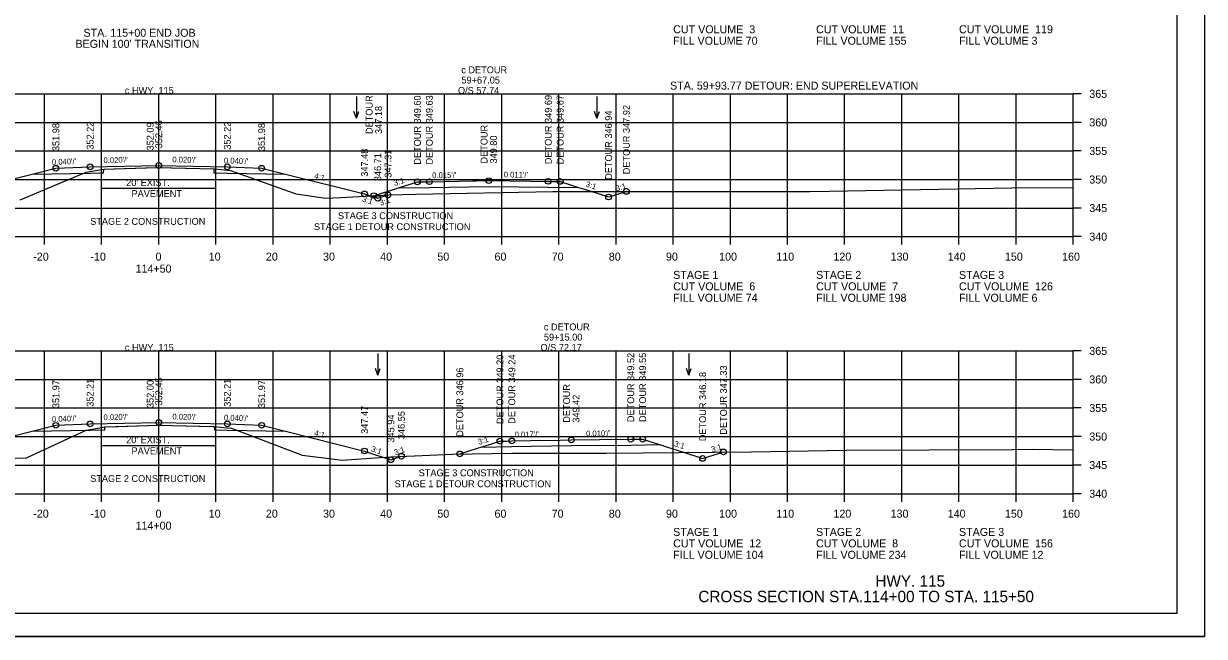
# Model space of a CAD drawing. Extents: x 1630712 to 1632516, y 782146 to 785403.
# Drawn here: x 1632309.3 to 1632515.9, y 784976.7 to 785083.9 of the extents above; entities that cross this region are included whole.
import ezdxf

# ---------------------------------------------------------------- set-up
doc = ezdxf.new("R2010")
doc.units = 0
for name, color, linetype in [('Notes', 7, 'Continuous'), ('R_Alt Surface', 7, 'Continuous'), ('R_Annot', 7, 'Continuous'), ('R_Axis', 7, 'Continuous'), ('R_Axis Annot', 7, 'Continuous'), ('R_Border', 7, 'Continuous'), ('R_Detour Subgrade', 7, 'Continuous'), ('R_Detour Surface', 7, 'Continuous'), ('R_Draft', 7, 'Continuous'), ('R_Exist Surface', 7, 'Continuous'), ('R_Fin Surface', 7, 'Continuous'), ('R_Grid', 7, 'Continuous'), ('R_No Plot', 7, 'Continuous'), ('R_Water Annot', 7, 'Continuous'), ('R_Xsect Elev', 7, 'Continuous'), ('R_Xsect Elev Detour', 7, 'Continuous'), ('R_Xsect Slope', 7, 'Continuous')]:
    doc.layers.add(name, color=color, linetype=linetype)

msp = doc.modelspace()

# ---------------------------------------------------------------- linework, layer by layer
at = {"layer": 'Notes'}
for p, q in [((1632322.96, 785053.45), (1632322.96, 785056.85)), ((1632342.96, 785053.45), (1632342.96, 785056.85)), ((1632322.96, 785055.15), (1632342.96, 785055.15)), ((1632322.96, 785008.41), (1632322.96, 785011.81)), ((1632322.96, 785010.11), (1632342.96, 785010.11)), ((1632342.96, 785008.41), (1632342.96, 785011.81))]:
    msp.add_line(p, q, dxfattribs=at)
at = {"layer": 'R_Alt Surface'}
for points in [[(1632310.79, 785057.59), (1632320.96, 785057.79), (1632323.28, 785057.83), (1632323.33, 785058.45), (1632332.68, 785058.74), (1632342.57, 785058.52), (1632342.62, 785057.84), (1632344.96, 785057.79), (1632355.14, 785057.59)], [(1632310.79, 785012.58), (1632320.96, 785012.78), (1632323.5, 785012.83), (1632323.55, 785013.35), (1632332.87, 785013.65), (1632342.67, 785013.4), (1632342.72, 785012.82), (1632344.96, 785012.78), (1632355.14, 785012.58)]]:
    msp.add_lwpolyline(points, dxfattribs=at)
at = {"layer": 'R_Axis'}
for p, q in [((1632492.96, 785046.65), (1632492.96, 785071.65)), ((1632494.36, 785071.65), (1632492.96, 785071.65)), ((1632494.36, 785066.65), (1632492.96, 785066.65)), ((1632494.36, 785061.65), (1632492.96, 785061.65)), ((1632494.36, 785056.65), (1632492.96, 785056.65)), ((1632494.36, 785051.65), (1632492.96, 785051.65)), ((1632212.96, 785046.65), (1632492.96, 785046.65)), ((1632312.96, 785045.25), (1632312.96, 785046.65)), ((1632322.96, 785045.25), (1632322.96, 785046.65)), ((1632332.96, 785045.25), (1632332.96, 785046.65)), ((1632342.96, 785045.25), (1632342.96, 785046.65)), ((1632352.96, 785045.25), (1632352.96, 785046.65)), ((1632362.96, 785045.25), (1632362.96, 785046.65)), ((1632372.96, 785045.25), (1632372.96, 785046.65)), ((1632382.96, 785045.25), (1632382.96, 785046.65)), ((1632392.96, 785045.25), (1632392.96, 785046.65)), ((1632402.96, 785045.25), (1632402.96, 785046.65)), ((1632412.96, 785045.25), (1632412.96, 785046.65)), ((1632422.96, 785045.25), (1632422.96, 785046.65)), ((1632432.96, 785045.25), (1632432.96, 785046.65)), ((1632442.96, 785045.25), (1632442.96, 785046.65)), ((1632452.96, 785045.25), (1632452.96, 785046.65)), ((1632462.96, 785045.25), (1632462.96, 785046.65)), ((1632472.96, 785045.25), (1632472.96, 785046.65)), ((1632482.96, 785045.25), (1632482.96, 785046.65)), ((1632492.96, 785045.25), (1632492.96, 785046.65)), ((1632494.36, 785046.65), (1632492.96, 785046.65)), ((1632492.96, 785001.65), (1632492.96, 785026.65)), ((1632494.36, 785026.65), (1632492.96, 785026.65)), ((1632494.36, 785021.65), (1632492.96, 785021.65)), ((1632494.36, 785016.65), (1632492.96, 785016.65)), ((1632494.36, 785011.65), (1632492.96, 785011.65)), ((1632494.36, 785006.65), (1632492.96, 785006.65)), ((1632212.96, 785001.65), (1632492.96, 785001.65)), ((1632312.96, 785000.25), (1632312.96, 785001.65)), ((1632322.96, 785000.25), (1632322.96, 785001.65)), ((1632332.96, 785000.25), (1632332.96, 785001.65)), ((1632342.96, 785000.25), (1632342.96, 785001.65)), ((1632352.96, 785000.25), (1632352.96, 785001.65)), ((1632362.96, 785000.25), (1632362.96, 785001.65)), ((1632372.96, 785000.25), (1632372.96, 785001.65)), ((1632382.96, 785000.25), (1632382.96, 785001.65)), ((1632392.96, 785000.25), (1632392.96, 785001.65)), ((1632402.96, 785000.25), (1632402.96, 785001.65)), ((1632412.96, 785000.25), (1632412.96, 785001.65)), ((1632422.96, 785000.25), (1632422.96, 785001.65)), ((1632432.96, 785000.25), (1632432.96, 785001.65)), ((1632442.96, 785000.25), (1632442.96, 785001.65)), ((1632452.96, 785000.25), (1632452.96, 785001.65)), ((1632462.96, 785000.25), (1632462.96, 785001.65)), ((1632472.96, 785000.25), (1632472.96, 785001.65)), ((1632482.96, 785000.25), (1632482.96, 785001.65)), ((1632492.96, 785000.25), (1632492.96, 785001.65)), ((1632494.36, 785001.65), (1632492.96, 785001.65))]:
    msp.add_line(p, q, dxfattribs=at)
at = {"layer": 'R_Border'}
for q in [(1632511.14, 785186.11), (1632194.96, 784980.65)]:
    msp.add_line((1632511.14, 784980.65), q, dxfattribs=at)
at = {"layer": 'R_Detour Subgrade'}
for points in [[(1632374.88, 785055.19), (1632380.3, 785055.27), (1632390.7, 785055.45), (1632401.11, 785055.33), (1632406.39, 785055.28)], [(1632389.32, 785009.79), (1632394.73, 785009.88), (1632405.14, 785010.07), (1632415.54, 785010.17), (1632420.64, 785010.23)]]:
    msp.add_lwpolyline(points, dxfattribs=at)
at = {"layer": 'R_Detour Surface'}
for points in [[(1632370.59, 785053.82), (1632371.64, 785054.16), (1632374.88, 785055.19), (1632378.03, 785056.18), (1632378.21, 785056.24), (1632378.31, 785056.24), (1632380.05, 785056.27), (1632380.3, 785056.27), (1632387.9, 785056.4), (1632388.49, 785056.41), (1632390.69, 785056.45), (1632390.7, 785056.45), (1632390.7, 785056.45), (1632398.08, 785056.36), (1632401.11, 785056.33), (1632402.25, 785056.32), (1632403.19, 785056.31), (1632404.99, 785055.73), (1632406.39, 785055.28), (1632406.79, 785055.15), (1632407.02, 785055.08), (1632408.37, 785054.65), (1632411.66, 785053.59), (1632412.13, 785053.74), (1632414.77, 785054.57)], [(1632385.63, 785008.61), (1632385.81, 785008.67), (1632387.12, 785009.09), (1632388.92, 785009.66), (1632389.32, 785009.79), (1632389.89, 785009.97), (1632392.65, 785010.85), (1632393.86, 785010.87), (1632394.73, 785010.88), (1632398.05, 785010.94), (1632403.16, 785011.03), (1632405.14, 785011.07), (1632405.15, 785011.07), (1632405.16, 785011.07), (1632410.06, 785011.11), (1632415.54, 785011.17), (1632416.56, 785011.18), (1632417.62, 785011.19), (1632419.82, 785010.49), (1632420.64, 785010.23), (1632421.15, 785010.06), (1632421.26, 785010.03), (1632421.99, 785009.79), (1632423.5, 785009.31), (1632427.29, 785008.09), (1632428.11, 785007.83), (1632430.91, 785008.71), (1632431.67, 785008.95)]]:
    msp.add_lwpolyline(points, dxfattribs=at)
at = {"layer": 'R_Exist Surface'}
for points in [[(1632308.69, 785053.12), (1632318.86, 785057.38), (1632320.24, 785057.94), (1632322.24, 785058.26), (1632323.33, 785058.45), (1632332.44, 785058.74), (1632332.68, 785058.74), (1632332.93, 785058.74), (1632342.57, 785058.52), (1632342.69, 785058.5), (1632345.52, 785058.22), (1632356.47, 785054.32), (1632356.81, 785054.2), (1632356.96, 785054.17), (1632362.18, 785053.37), (1632364.83, 785053.51), (1632373.23, 785053.97), (1632377.91, 785054.07), (1632401.93, 785054.56), (1632402.15, 785054.56), (1632402.26, 785054.57), (1632404.14, 785054.57), (1632446.79, 785054.57), (1632450.27, 785054.61), (1632482.2, 785055.18), (1632492.96, 785055.27)], [(1632304.03, 785007.76), (1632309.82, 785007.95), (1632317.08, 785011.32), (1632320.26, 785012.77), (1632322.63, 785013.19), (1632323.55, 785013.35), (1632325.83, 785013.43), (1632332.87, 785013.65), (1632340.02, 785013.47), (1632342.67, 785013.4), (1632344.84, 785013.19), (1632345.66, 785013.1), (1632349.17, 785011.79), (1632358.05, 785008.39), (1632363.21, 785007.75), (1632365.03, 785007.49), (1632371.63, 785007.99), (1632373.68, 785008.12), (1632384.41, 785008.59), (1632394.72, 785008.77), (1632411.25, 785008.74), (1632436.67, 785009), (1632453.23, 785009.26), (1632482.27, 785009.39), (1632485.78, 785009.43), (1632492.96, 785009.3)]]:
    msp.add_lwpolyline(points, dxfattribs=at)
at = {"layer": 'R_Fin Surface'}
for points in [[(1632291.9, 785053.15), (1632292.96, 785052.8), (1632296.96, 785054.13), (1632310.79, 785057.59), (1632314.96, 785058.63), (1632320.96, 785058.87), (1632332.96, 785059.11), (1632344.96, 785058.87), (1632350.96, 785058.63), (1632355.14, 785057.59), (1632368.96, 785054.13), (1632371.27, 785053.36), (1632373.07, 785053.96)], [(1632290.83, 785008.01), (1632292.24, 785007.55), (1632296.96, 785009.12), (1632310.79, 785012.58), (1632314.96, 785013.62), (1632320.96, 785013.86), (1632332.96, 785014.1), (1632344.96, 785013.86), (1632350.96, 785013.62), (1632355.14, 785012.58), (1632368.96, 785009.12), (1632373.57, 785007.59), (1632375.41, 785008.2)]]:
    msp.add_lwpolyline(points, dxfattribs=at)
at = {"layer": 'R_Grid'}
for p, q in [((1632212.96, 785071.65), (1632492.96, 785071.65)), ((1632312.96, 785046.65), (1632312.96, 785071.65)), ((1632322.96, 785046.65), (1632322.96, 785071.65)), ((1632332.96, 785046.65), (1632332.96, 785071.65)), ((1632342.96, 785046.65), (1632342.96, 785071.65)), ((1632352.96, 785046.65), (1632352.96, 785071.65)), ((1632362.96, 785046.65), (1632362.96, 785071.65)), ((1632372.96, 785046.65), (1632372.96, 785071.65)), ((1632382.96, 785046.65), (1632382.96, 785071.65)), ((1632392.96, 785046.65), (1632392.96, 785071.65)), ((1632402.96, 785046.65), (1632402.96, 785071.65)), ((1632412.96, 785046.65), (1632412.96, 785071.65)), ((1632422.96, 785046.65), (1632422.96, 785071.65)), ((1632432.96, 785046.65), (1632432.96, 785071.65)), ((1632442.96, 785046.65), (1632442.96, 785071.65)), ((1632452.96, 785046.65), (1632452.96, 785071.65)), ((1632462.96, 785046.65), (1632462.96, 785071.65)), ((1632472.96, 785046.65), (1632472.96, 785071.65)), ((1632482.96, 785046.65), (1632482.96, 785071.65)), ((1632492.96, 785046.65), (1632492.96, 785071.65)), ((1632212.96, 785066.65), (1632492.96, 785066.65)), ((1632212.96, 785061.65), (1632492.96, 785061.65)), ((1632212.96, 785056.65), (1632492.96, 785056.65)), ((1632212.96, 785051.65), (1632492.96, 785051.65)), ((1632212.96, 785046.65), (1632492.96, 785046.65)), ((1632212.96, 785026.65), (1632492.96, 785026.65)), ((1632312.96, 785001.65), (1632312.96, 785026.65)), ((1632322.96, 785001.65), (1632322.96, 785026.65)), ((1632332.96, 785001.65), (1632332.96, 785026.65)), ((1632342.96, 785001.65), (1632342.96, 785026.65)), ((1632352.96, 785001.65), (1632352.96, 785026.65)), ((1632362.96, 785001.65), (1632362.96, 785026.65)), ((1632372.96, 785001.65), (1632372.96, 785026.65)), ((1632382.96, 785001.65), (1632382.96, 785026.65)), ((1632392.96, 785001.65), (1632392.96, 785026.65)), ((1632402.96, 785001.65), (1632402.96, 785026.65)), ((1632412.96, 785001.65), (1632412.96, 785026.65)), ((1632422.96, 785001.65), (1632422.96, 785026.65)), ((1632432.96, 785001.65), (1632432.96, 785026.65)), ((1632442.96, 785001.65), (1632442.96, 785026.65)), ((1632452.96, 785001.65), (1632452.96, 785026.65)), ((1632462.96, 785001.65), (1632462.96, 785026.65)), ((1632472.96, 785001.65), (1632472.96, 785026.65)), ((1632482.96, 785001.65), (1632482.96, 785026.65)), ((1632492.96, 785001.65), (1632492.96, 785026.65)), ((1632212.96, 785021.65), (1632492.96, 785021.65)), ((1632212.96, 785016.65), (1632492.96, 785016.65)), ((1632212.96, 785011.65), (1632492.96, 785011.65)), ((1632212.96, 785006.65), (1632492.96, 785006.65)), ((1632212.96, 785001.65), (1632492.96, 785001.65))]:
    msp.add_line(p, q, dxfattribs=at)
at = {"layer": 'R_No Plot'}
msp.add_line((1632182.56, 784976.67), (1632515.9, 784976.67), dxfattribs=at)
msp.add_lwpolyline([(1632182.56, 785190), (1632515.9, 785190), (1632515.9, 784976.66), (1632182.56, 784976.66)], close=True, dxfattribs=at)
for centre in [(1632314.96, 785058.63), (1632320.96, 785058.87), (1632332.96, 785059.11), (1632344.96, 785058.87), (1632350.96, 785058.63), (1632378.21, 785056.24), (1632380.3, 785056.27), (1632390.7, 785056.45), (1632401.11, 785056.33), (1632403.19, 785056.31), (1632368.96, 785054.13), (1632370.59, 785053.82), (1632371.27, 785053.36), (1632373.07, 785053.96), (1632411.66, 785053.59), (1632414.77, 785054.57), (1632320.96, 785013.86), (1632332.96, 785014.1), (1632344.96, 785013.86), (1632314.96, 785013.62), (1632350.96, 785013.62), (1632392.65, 785010.85), (1632394.73, 785010.88), (1632405.14, 785011.07), (1632415.54, 785011.17), (1632417.62, 785011.19), (1632368.96, 785009.12), (1632373.57, 785007.59), (1632375.41, 785008.2), (1632385.63, 785008.61), (1632428.11, 785007.83), (1632431.76, 785008.97)]:
    msp.add_circle(centre, 0.5, dxfattribs=at)
at = {"layer": 'R_Water Annot'}
for p, q in [((1632367.53, 785071.17), (1632367.53, 785067.4)), ((1632409.63, 785071.17), (1632409.63, 785067.4)), ((1632367.53, 785067.4), (1632367.11, 785068.56)), ((1632367.53, 785067.4), (1632367.95, 785068.56)), ((1632409.63, 785067.4), (1632409.21, 785068.56)), ((1632409.63, 785067.4), (1632410.05, 785068.56)), ((1632371.27, 785026.18), (1632371.27, 785022.41)), ((1632425.7, 785026.18), (1632425.7, 785022.41)), ((1632371.27, 785022.41), (1632370.85, 785023.57)), ((1632371.27, 785022.41), (1632371.69, 785023.57)), ((1632425.7, 785022.41), (1632425.28, 785023.57)), ((1632425.7, 785022.41), (1632426.12, 785023.57))]:
    msp.add_line(p, q, dxfattribs=at)

# ---------------------------------------------------------------- texts
at = {"layer": 'Notes'}
for s, p in [('c DETOUR', (1632385.89, 785075.25)), ('59+67.05', (1632385.91, 785073.45)), ('c HWY. 115', (1632327.02, 785071.65)), ('O/S 57.74', (1632385.31, 785071.65)), ("20' EXIST.", (1632327.26, 785055.51)), ('PAVEMENT', (1632328.19, 785053.59)), ('STAGE 2 CONSTRUCTION', (1632320.96, 785048.72)), ('STAGE 3 CONSTRUCTION', (1632364.31, 785049.71)), ('STAGE 1 DETOUR CONSTRUCTION', (1632360.11, 785047.79)), ('c DETOUR', (1632400.33, 785030.25)), ('59+15.00', (1632400.34, 785028.45)), ('c HWY. 115', (1632327.02, 785026.65)), ('O/S 72.17', (1632399.74, 785026.65)), ("20' EXIST.", (1632327.26, 785010.47)), ('PAVEMENT', (1632328.19, 785008.55)), ('STAGE 3 CONSTRUCTION', (1632378.43, 785004.7)), ('STAGE 2 CONSTRUCTION', (1632320.96, 785003.7)), ('STAGE 1 DETOUR CONSTRUCTION', (1632374.23, 785002.78))]:
    msp.add_text(s, height=1.2, dxfattribs=at).set_placement(p)
at = {"layer": 'R_Annot'}
for s, p in [('STA. 115+00 END JOB', (1632319.79, 785081.64)), ("BEGIN 100' TRANSITION", (1632318.38, 785079.71)), ('STA. 59+93.77 DETOUR: END SUPERELEVATION', (1632422.41, 785072.39))]:
    msp.add_text(s, height=1.4, dxfattribs=at).set_placement(p)
at = {"layer": 'R_Axis Annot'}
for s, p in [('CUT VOLUME  3', (1632422.96, 785082.25)), ('CUT VOLUME  11', (1632447.96, 785082.25)), ('CUT VOLUME  119', (1632472.96, 785082.25)), ('FILL VOLUME 70', (1632422.96, 785080.25)), ('FILL VOLUME 155', (1632447.96, 785080.25)), ('FILL VOLUME 3', (1632472.96, 785080.25)), ('365', (1632495.76, 785070.95)), ('360', (1632495.76, 785065.95)), ('355', (1632495.76, 785060.95)), ('350', (1632495.76, 785055.95)), ('345', (1632495.76, 785050.95)), ('340', (1632495.76, 785045.95)), ('-20', (1632311, 785042.45)), ('-10', (1632321, 785042.45)), ('0', (1632332.4, 785042.45)), ('10', (1632341.7, 785042.45)), ('20', (1632351.7, 785042.45)), ('30', (1632361.7, 785042.45)), ('40', (1632371.7, 785042.45)), ('50', (1632381.7, 785042.45)), ('60', (1632391.7, 785042.45)), ('70', (1632401.7, 785042.45)), ('80', (1632411.7, 785042.45)), ('90', (1632421.7, 785042.45)), ('100', (1632431, 785042.45)), ('110', (1632441, 785042.45)), ('120', (1632451, 785042.45)), ('130', (1632461, 785042.45)), ('140', (1632471, 785042.45)), ('150', (1632481, 785042.45)), ('160', (1632491, 785042.45)), ('114+50', (1632328.9, 785040.35)), ('STAGE 1', (1632422.96, 785039.25)), ('STAGE 2', (1632447.96, 785039.25)), ('STAGE 3', (1632472.96, 785039.25)), ('CUT VOLUME  6', (1632422.96, 785037.25)), ('CUT VOLUME  7', (1632447.96, 785037.25)), ('CUT VOLUME  126', (1632472.96, 785037.25)), ('FILL VOLUME 74', (1632422.96, 785035.25)), ('FILL VOLUME 198', (1632447.96, 785035.25)), ('FILL VOLUME 6', (1632472.96, 785035.25)), ('365', (1632495.76, 785025.95)), ('360', (1632495.76, 785020.95)), ('355', (1632495.76, 785015.95)), ('350', (1632495.76, 785010.95)), ('345', (1632495.76, 785005.95)), ('340', (1632495.76, 785000.95)), ('-20', (1632311, 784997.45)), ('-10', (1632321, 784997.45)), ('0', (1632332.4, 784997.45)), ('10', (1632341.7, 784997.45)), ('20', (1632351.7, 784997.45)), ('30', (1632361.7, 784997.45)), ('40', (1632371.7, 784997.45)), ('50', (1632381.7, 784997.45)), ('60', (1632391.7, 784997.45)), ('70', (1632401.7, 784997.45)), ('80', (1632411.7, 784997.45)), ('90', (1632421.7, 784997.45)), ('100', (1632431, 784997.45)), ('110', (1632441, 784997.45)), ('120', (1632451, 784997.45)), ('130', (1632461, 784997.45)), ('140', (1632471, 784997.45)), ('150', (1632481, 784997.45)), ('160', (1632491, 784997.45)), ('114+00', (1632328.9, 784995.35)), ('STAGE 1', (1632422.96, 784994.25)), ('STAGE 2', (1632447.96, 784994.25)), ('STAGE 3', (1632472.96, 784994.25)), ('CUT VOLUME  12', (1632422.96, 784992.25)), ('CUT VOLUME  8', (1632447.96, 784992.25)), ('CUT VOLUME  156', (1632472.96, 784992.25)), ('FILL VOLUME 104', (1632422.96, 784990.25)), ('FILL VOLUME 234', (1632447.96, 784990.25)), ('FILL VOLUME 12', (1632472.96, 784990.25))]:
    msp.add_text(s, height=1.4, dxfattribs=at).set_placement(p)
at = {"layer": 'R_Draft'}
for s, p in [('HWY. 115', (1632458.34, 784985.36)), ('CROSS SECTION STA.114+00 TO STA. 115+50', (1632427.36, 784982.65))]:
    msp.add_text(s, height=2, dxfattribs=at).set_placement(p)
at = {"layer": 'R_Xsect Elev'}
for s, p in [('351.98', (1632315.56, 785061.63)), ('352.22', (1632321.56, 785061.87)), ('352.09', (1632332.06, 785061.74)), ('352.46', (1632333.56, 785062.11)), ('352.22', (1632345.56, 785061.87)), ('351.98', (1632351.56, 785061.63)), ('347.48', (1632369.56, 785057.13)), ('347.31', (1632373.67, 785056.96)), ('346.71', (1632371.87, 785056.36)), ('351.97', (1632315.56, 785016.62)), ('352.21', (1632321.56, 785016.86)), ('352.00', (1632332.06, 785016.64)), ('352.45', (1632333.56, 785017.1)), ('352.21', (1632345.56, 785016.86)), ('351.97', (1632351.56, 785016.62)), ('347.47', (1632369.56, 785012.12)), ('345.94', (1632374.17, 785010.59)), ('346.55', (1632376.01, 785011.2))]:
    msp.add_text(s, height=1.2, rotation=90, dxfattribs=at).set_placement(p)
at = {"layer": 'R_Xsect Elev Detour'}
for s, p in [('DETOUR', (1632370.37, 785064.62)), ('DETOUR 349.60', (1632378.81, 785059.24)), ('DETOUR 349.63', (1632380.9, 785059.27)), ('DETOUR 349.69', (1632401.71, 785059.33)), ('DETOUR 349.67', (1632403.79, 785059.31)), ('347.18', (1632372.02, 785064.62)), ('DETOUR 346.94', (1632412.26, 785056.59)), ('DETOUR 347.92', (1632415.37, 785057.57)), ('DETOUR', (1632390.48, 785059.45)), ('349.80', (1632392.13, 785059.45)), ('DETOUR 349.20', (1632393.25, 785013.85)), ('DETOUR 349.24', (1632395.33, 785013.88)), ('DETOUR 349.52', (1632416.14, 785014.17)), ('DETOUR 349.55', (1632418.22, 785014.19)), ('DETOUR 346.96', (1632386.23, 785011.61)), ('DETOUR 346.18', (1632428.71, 785010.83)), ('DETOUR 347.33', (1632432.36, 785011.97)), ('DETOUR', (1632404.91, 785014.07)), ('349.42', (1632406.56, 785014.07))]:
    msp.add_text(s, height=1.2, rotation=90, dxfattribs=at).set_placement(p)
at = {"layer": 'R_Xsect Slope'}
for s, rotation, p in [("0.040'/'", 2.2906, (1632314.29, 785059.2)), ("0.020'/'", 1.1458, (1632323.3, 785059.52)), ("0.020'/'", 358.8542, (1632335.33, 785059.66)), ("0.040'/'", 357.7094, (1632344.34, 785059.5)), ('4:1', 345.9638, (1632360.09, 785056.86)), ("0.015'/'", 0.9296, (1632380.8, 785056.88)), ("0.011'/'", 359.3844, (1632393.31, 785057.02)), ('3:1', 17.6037, (1632374.25, 785055.51)), ('3:1', 342.1711, (1632407.58, 785055.43)), ('3:1', 17.4101, (1632413.06, 785054.55)), ('3:1', 341.5651, (1632368.46, 785052.83)), ('3:1', 18.4349, (1632371.78, 785052.04)), ("0.040'/'", 2.2906, (1632314.29, 785014.19)), ("0.020'/'", 1.1458, (1632323.3, 785014.51)), ("0.020'/'", 358.8542, (1632335.33, 785014.65)), ("0.040'/'", 357.7094, (1632344.34, 785014.49)), ('4:1', 345.9638, (1632360.09, 785011.86)), ("0.017'/'", 1.0134, (1632395.23, 785011.49)), ("0.010'/'", 0.5638, (1632407.72, 785011.69)), ('3:1', 17.6853, (1632388.99, 785010.2)), ('3:1', 342.2197, (1632423.02, 785009.99)), ('3:1', 17.4044, (1632429.78, 785008.88)), ('3:1', 341.5651, (1632370.02, 785009.08)), ('3:1', 18.4349, (1632374.33, 785008.37))]:
    msp.add_text(s, height=1, rotation=rotation, dxfattribs=at).set_placement(p)

doc.saveas('drawing.dxf')
